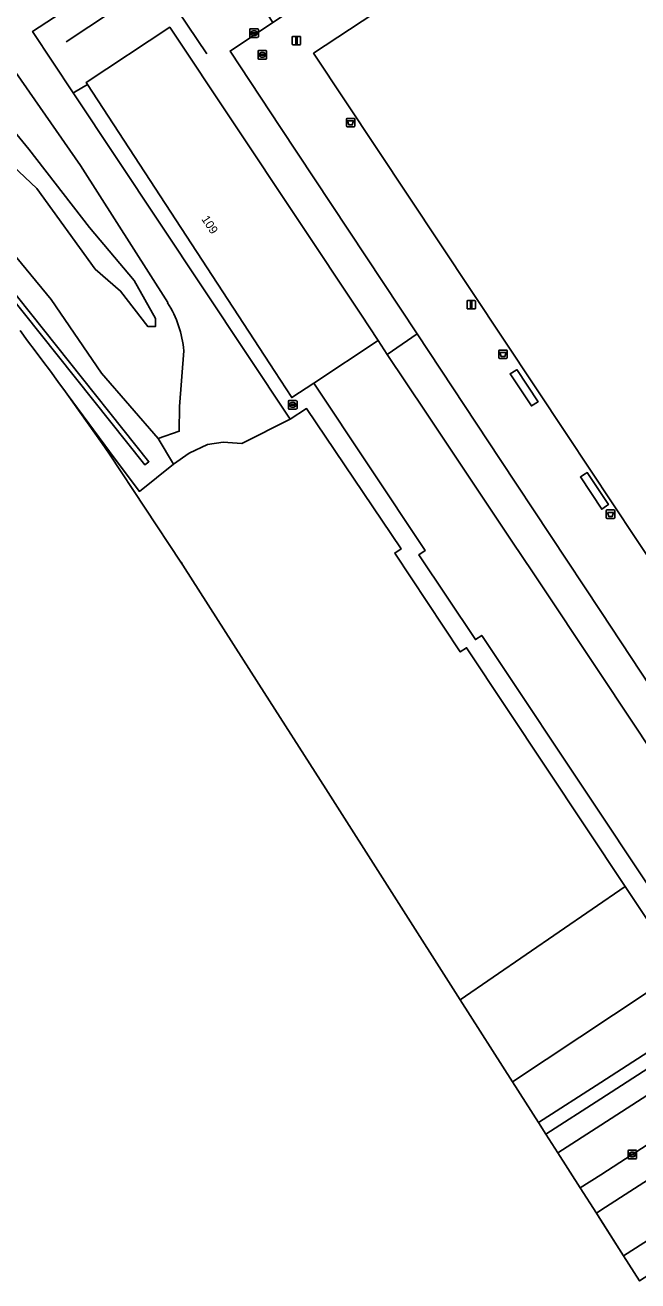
# Model space of a CAD drawing. Extents: x 155640 to 156811, y 382821 to 384049.
# Drawn here: x 156432.6 to 156504.4, y 382835.2 to 382982.3 of the extents above; entities that cross this region are included whole.
import ezdxf

# ---------------------------------------------------------------- set-up
doc = ezdxf.new("R2010")
doc.units = 0
for name, color, linetype in [('IMGEO_Afvalbak', 7, 'Continuous'), ('IMGEO_Berm_groen', 7, 'Continuous'), ('IMGEO_Erf', 7, 'Continuous'), ('IMGEO_Fietspad_gesloten', 7, 'Continuous'), ('IMGEO_Groenvoorziening', 7, 'Continuous'), ('IMGEO_Hek', 7, 'Continuous'), ('IMGEO_Kolk', 7, 'Continuous'), ('IMGEO_Lichtmast', 7, 'Continuous'), ('IMGEO_Pand', 7, 'Continuous'), ('IMGEO_Pand_nummerreeks', 7, 'Continuous'), ('IMGEO_Rijbaan_regionaal_gesloten', 7, 'Continuous'), ('IMGEO_Rioolput', 7, 'Continuous'), ('IMGEO_Terreindeel_gesloten', 7, 'Continuous'), ('IMGEO_Voetpad_gesloten', 7, 'Continuous'), ('IMGEO_Voetpad_open', 7, 'Continuous')]:
    doc.layers.add(name, color=color, linetype=linetype)

msp = doc.modelspace()

# ---------------------------------------------------------------- linework, layer by layer
at = {"layer": 'IMGEO_Afvalbak'}
for p, q in [((156470.21, 382970.51), (156470.21, 382971.31)), ((156470.21, 382971.31), (156470.21, 382970.51)), ((156470.31, 382971.41), (156471.09, 382971.41)), ((156471.09, 382971.41), (156470.31, 382971.41)), ((156471.09, 382970.41), (156470.31, 382970.41)), ((156470.31, 382970.41), (156471.09, 382970.41)), ((156471.19, 382971.31), (156471.19, 382970.51)), ((156471.19, 382970.51), (156471.19, 382971.31)), ((156488.06, 382943.37), (156488.06, 382944.17)), ((156488.06, 382944.17), (156488.06, 382943.37)), ((156488.16, 382944.27), (156488.95, 382944.27)), ((156488.95, 382944.27), (156488.16, 382944.27)), ((156489.05, 382944.17), (156489.05, 382943.37)), ((156489.05, 382943.37), (156489.05, 382944.17)), ((156488.95, 382943.27), (156488.16, 382943.27)), ((156488.16, 382943.27), (156488.95, 382943.27)), ((156500.65, 382924.64), (156500.65, 382925.44)), ((156500.65, 382925.44), (156500.65, 382924.64)), ((156500.75, 382925.54), (156501.54, 382925.54)), ((156501.54, 382925.54), (156500.75, 382925.54)), ((156501.64, 382925.44), (156501.64, 382924.64)), ((156501.64, 382924.64), (156501.64, 382925.44)), ((156501.54, 382924.54), (156500.75, 382924.54)), ((156500.75, 382924.54), (156501.54, 382924.54))]:
    msp.add_line(p, q, dxfattribs=at)
for points in [[(156470.35, 382971.13), (156471.05, 382971.13), (156470.9, 382970.65), (156470.5, 382970.65), (156470.35, 382971.13)], [(156488.2, 382943.99), (156488.91, 382943.99), (156488.76, 382943.51), (156488.35, 382943.51), (156488.2, 382943.99)], [(156500.79, 382925.25), (156501.5, 382925.25), (156501.35, 382924.78), (156500.94, 382924.78), (156500.79, 382925.25)]]:
    msp.add_lwpolyline(points, dxfattribs=at)
for centre, start, end in [((156470.31, 382971.31), 90, 180), ((156470.31, 382971.31), 90, 180), ((156470.31, 382970.51), 180, 270), ((156470.31, 382970.51), 180, 270), ((156471.09, 382971.31), 0, 90), ((156471.09, 382971.31), 360, 90), ((156471.09, 382970.51), 270, 0), ((156471.09, 382970.51), 270, 0), ((156488.16, 382944.17), 90, 180), ((156488.16, 382944.17), 90, 180), ((156488.95, 382944.17), 0, 90), ((156488.95, 382944.17), 360, 90), ((156488.16, 382943.37), 180, 270), ((156488.16, 382943.37), 180, 270), ((156488.95, 382943.37), 270, 0), ((156488.95, 382943.37), 270, 0), ((156500.75, 382925.44), 90, 180), ((156500.75, 382925.44), 90, 180), ((156501.54, 382925.44), 0, 90), ((156501.54, 382925.44), 360, 90), ((156500.75, 382924.64), 180, 270), ((156500.75, 382924.64), 180, 270), ((156501.54, 382924.64), 270, 0), ((156501.54, 382924.64), 270, 0)]:
    msp.add_arc(centre, 0.1, start, end, dxfattribs=at)
at = {"layer": 'IMGEO_Berm_groen'}
for points in [[(156551.36, 382886.6), (156549.21, 382885.22), (156500, 382853.47), (156494.97, 382850.22), (156497.6, 382846.1), (156500, 382847.64), (156503.7, 382850.02), (156518.86, 382859.79), (156534.39, 382869.79), (156551.62, 382880.87)], [(156556.43, 382879.8), (156500, 382843.48)], [(156500, 382843.48), (156499.49, 382843.15), (156502.68, 382838.15), (156506.01, 382840.3), (156509.37, 382842.45), (156512.6, 382844.84), (156532.14, 382860.54)]]:
    msp.add_lwpolyline(points, dxfattribs=at)
at = {"layer": 'IMGEO_Erf'}
msp.add_lwpolyline([(156450.82, 382919.42), (156450.83, 382919.42), (156451.06, 382919.06), (156451.06, 382919.06), (156459.96, 382905.11), (156467.78, 382892.85), (156467.78, 382892.85), (156483.53, 382868.15), (156502.87, 382881.43), (156484.28, 382909.39), (156483.55, 382908.9), (156475.87, 382920.48), (156476.61, 382920.96), (156465.54, 382937.4), (156463.61, 382936.15), (156457.95, 382933.32), (156455.75, 382933.47), (156453.93, 382933.22), (156451.77, 382932.2), (156449.96, 382930.89), (156445.96, 382927.71), (156443.13, 382931.5), (156437.49, 382939.08), (156438.16, 382938.16), (156439.02, 382936.95), (156439.89, 382935.73), (156440.74, 382934.52), (156441.6, 382933.3), (156442.45, 382932.07)], close=True, dxfattribs=at)
at = {"layer": 'IMGEO_Fietspad_gesloten'}
msp.add_lwpolyline([(156548.16, 382887.64), (156500, 382856.53), (156493.59, 382852.39), (156494.97, 382850.22), (156500, 382853.47), (156549.21, 382885.22), (156551.36, 382886.6)], dxfattribs=at)
at = {"layer": 'IMGEO_Groenvoorziening'}
for points in [[(156251.71, 383103.22), (156317.77, 383054.79), (156319.51, 383051.96), (156359.06, 383022.72), (156397.9, 382989.3), (156414.08, 382971.59), (156446.59, 382930.82), (156447.07, 382931.18), (156414.55, 382971.96), (156398.38, 382989.67), (156359.53, 383023.09), (156319.98, 383052.32), (156318.24, 383055.16), (156252.18, 383103.58), (156251.81, 383103.29)], [(156359.53, 383023.09), (156398.38, 382989.67), (156414.55, 382971.96), (156447.07, 382931.18), (156446.59, 382930.82), (156414.08, 382971.59), (156397.9, 382989.3), (156359.06, 383022.72), (156319.51, 383051.96), (156317.77, 383054.79), (156251.71, 383103.22), (156251.81, 383103.29), (156252.18, 383103.58), (156318.24, 383055.16), (156319.98, 383052.32)], [(156483.53, 382868.15), (156489.68, 382858.52), (156509.39, 382871.62), (156502.87, 382881.43)], [(156499.49, 382843.15), (156500, 382842.34), (156502.68, 382838.15)]]:
    msp.add_lwpolyline(points, close=True, dxfattribs=at)
for points in [[(156255.05, 383103.49), (156264.43, 383096.48), (156294.23, 383074.54), (156313.79, 383060.73), (156336.14, 383043.58), (156363.98, 383022.66), (156379.55, 383010.3), (156403.91, 382988.08), (156421.5, 382967.29), (156435.6, 382950.17), (156441.51, 382941.55), (156448.16, 382933.9), (156450.62, 382934.76), (156450.67, 382937.67), (156451.15, 382944.19)], [(156451.15, 382944.19), (156450.67, 382937.67), (156450.62, 382934.76), (156448.16, 382933.9), (156449.96, 382930.89), (156451.77, 382932.2), (156453.93, 382933.22), (156455.75, 382933.47), (156457.95, 382933.32), (156463.61, 382936.15), (156438.21, 382974.39), (156433.44, 382981.59), (156440.92, 382986.52), (156439.33, 382988.35), (156371.47, 383038.23)], [(156449.27, 382949.82), (156439.05, 382965.88), (156430.86, 382977.69), (156429.53, 382979.73), (156426.61, 382985.01)], [(156426.61, 382985.01), (156429.53, 382979.73), (156430.86, 382977.69), (156439.05, 382965.88), (156449.27, 382949.82)], [(156421.12, 382975.25), (156433.92, 382963.21), (156440.78, 382953.74), (156443.76, 382951.17), (156446.93, 382947.03), (156447.86, 382947.03), (156447.86, 382947.96), (156445.36, 382952.4), (156440.09, 382958.61), (156433.01, 382967.82), (156425.56, 382976.88)], [(156425.56, 382976.88), (156433.01, 382967.82), (156440.09, 382958.61), (156445.36, 382952.4), (156447.86, 382947.96), (156447.86, 382947.03), (156446.93, 382947.03), (156443.76, 382951.17), (156440.78, 382953.74), (156433.92, 382963.21), (156421.12, 382975.25)], [(156431.97, 382946.55), (156432.86, 382945.36), (156433.76, 382944.17), (156434.65, 382942.98), (156435.53, 382941.78), (156436.41, 382940.58), (156437.29, 382939.37), (156437.49, 382939.08), (156443.13, 382931.5), (156445.96, 382927.71), (156449.96, 382930.89), (156448.16, 382933.9), (156441.51, 382941.55), (156435.6, 382950.17), (156421.5, 382967.29)], [(156591.61, 382925.65), (156590.83, 382925.47), (156590.77, 382925.43), (156590.12, 382924.99), (156522.16, 382880.06), (156511.09, 382872.74), (156509.39, 382871.62), (156489.68, 382858.52), (156492.71, 382853.76), (156500, 382858.46), (156547.39, 382889.03)]]:
    msp.add_lwpolyline(points, dxfattribs=at)
msp.add_arc((156438.83, 382943.19), 12.36, 4.6367, 32.4104, dxfattribs=at)
msp.add_arc((156438.83, 382943.19), 12.36, 4.6367, 32.4104, dxfattribs=at)
at = {"layer": 'IMGEO_Hek'}
for points in [[(156439.33, 382988.35), (156440.92, 382986.52), (156433.44, 382981.59), (156438.21, 382974.39)], [(156437.38, 382980.39), (156448.13, 382987.51), (156453.85, 382978.96)], [(156438.36, 382974.48), (156439.88, 382975.38)], [(156438.21, 382974.39), (156438.36, 382974.48)], [(156438.21, 382974.39), (156463.61, 382936.15), (156465.54, 382937.4), (156476.61, 382920.96)], [(156443.13, 382931.5), (156437.49, 382939.08)], [(156476.61, 382920.96), (156475.87, 382920.48), (156483.55, 382908.9), (156484.28, 382909.39), (156502.87, 382881.43), (156509.39, 382871.62)]]:
    msp.add_lwpolyline(points, dxfattribs=at)
at = {"layer": 'IMGEO_Kolk'}
for p, q in [((156459.86, 382978.43), (156459.86, 382979.28)), ((156459.94, 382979.36), (156460.79, 382979.36)), ((156460.86, 382979.28), (156460.86, 382978.43)), ((156460.79, 382978.35), (156459.94, 382978.35)), ((156460.12, 382978.85), (156460.12, 382978.86)), ((156460.16, 382978.9), (156460.56, 382978.9)), ((156460.56, 382978.81), (156460.16, 382978.81)), ((156460.35, 382979.13), (156460.37, 382979.13)), ((156460.37, 382978.58), (156460.35, 382978.58)), ((156460.6, 382978.86), (156460.6, 382978.85)), ((156503.2, 382849.59), (156503.2, 382850.44)), ((156503.28, 382850.52), (156504.13, 382850.52)), ((156503.46, 382850.01), (156503.46, 382850.02)), ((156503.5, 382850.06), (156503.9, 382850.06)), ((156503.9, 382849.97), (156503.5, 382849.97)), ((156503.69, 382850.3), (156503.72, 382850.3)), ((156503.71, 382849.74), (156503.69, 382849.74)), ((156503.95, 382850.02), (156503.95, 382850.01)), ((156504.2, 382850.44), (156504.2, 382849.59)), ((156504.13, 382849.52), (156503.28, 382849.52))]:
    msp.add_line(p, q, dxfattribs=at)
for points in [[(156459.86, 382978.43), (156459.86, 382979.28)], [(156459.94, 382979.36), (156460.79, 382979.36)], [(156460.86, 382979.28), (156460.86, 382978.43)], [(156460.79, 382978.35), (156459.94, 382978.35)], [(156503.2, 382849.59), (156503.2, 382850.44)], [(156503.28, 382850.52), (156504.13, 382850.52)], [(156504.2, 382850.44), (156504.2, 382849.59)], [(156504.13, 382849.52), (156503.28, 382849.52)]]:
    msp.add_lwpolyline(points, dxfattribs=at)
for centre, radius, start, end in [((156459.94, 382979.28), 0.0765, 91.552, 178.448), ((156459.94, 382979.28), 0.0765, 91.552, 178.448), ((156460.79, 382979.28), 0.0765, 1.552, 88.448), ((156460.79, 382979.28), 0.0765, 1.552, 88.448), ((156459.94, 382978.43), 0.0765, 181.552, 268.448), ((156459.94, 382978.43), 0.0765, 181.552, 268.448), ((156460.16, 382978.86), 0.0403, 85.8775, 175.7526), ((156460.16, 382978.85), 0.0366, 178.938, 274.7102), ((156460.57, 382978.86), 0.0386, 1.7309, 96.639), ((156460.56, 382978.85), 0.043, 264.8664, 352.4533), ((156460.79, 382978.43), 0.0765, 271.552, 358.448), ((156460.79, 382978.43), 0.0765, 271.552, 358.448), ((156503.28, 382850.44), 0.0765, 91.552, 178.448), ((156503.28, 382850.44), 0.0765, 91.552, 178.448), ((156503.5, 382850.02), 0.0403, 85.8775, 175.7526), ((156503.5, 382850.01), 0.0366, 178.938, 274.7102), ((156503.91, 382850.02), 0.0386, 1.7309, 96.639), ((156503.9, 382850.02), 0.043, 264.8664, 352.4533), ((156504.13, 382850.44), 0.0765, 1.552, 88.448), ((156504.13, 382850.44), 0.0765, 1.552, 88.448), ((156503.28, 382849.59), 0.0765, 181.552, 268.448), ((156503.28, 382849.59), 0.0765, 181.552, 268.448), ((156504.13, 382849.59), 0.0765, 271.552, 358.448), ((156504.13, 382849.59), 0.0765, 271.552, 358.448)]:
    msp.add_arc(centre, radius, start, end, dxfattribs=at)
for centre, major_axis, ratio, start_param, end_param in [((156460.35, 382978.85), (-0.387, 0.002), 0.722429, 4.712389, 7.853982), ((156460.37, 382978.85), (-0.39, 0.002), 0.717154, 1.570796, 4.712389), ((156503.69, 382850.02), (-0.387, 0.002), 0.722429, 4.712389, 7.853982), ((156503.71, 382850.02), (-0.39, 0.002), 0.717154, 1.570796, 4.712389)]:
    msp.add_ellipse(centre, major_axis=major_axis, ratio=ratio, start_param=start_param, end_param=end_param, dxfattribs=at)
at = {"layer": 'IMGEO_Lichtmast'}
for p, q in [((156463.85, 382980.12), (156463.85, 382980.92)), ((156463.85, 382980.92), (156463.85, 382980.12)), ((156463.95, 382981.02), (156464.74, 382981.02)), ((156464.74, 382981.02), (156463.95, 382981.02)), ((156464.84, 382980.92), (156464.84, 382980.12)), ((156464.84, 382980.12), (156464.84, 382980.92)), ((156464.74, 382980.02), (156463.95, 382980.02)), ((156463.95, 382980.02), (156464.74, 382980.02)), ((156484.34, 382949.18), (156484.34, 382949.97)), ((156484.34, 382949.97), (156484.34, 382949.18)), ((156484.44, 382950.07), (156485.22, 382950.07)), ((156485.22, 382950.07), (156484.44, 382950.07)), ((156485.32, 382949.97), (156485.32, 382949.18)), ((156485.32, 382949.18), (156485.32, 382949.97)), ((156485.22, 382949.08), (156484.44, 382949.08)), ((156484.44, 382949.08), (156485.22, 382949.08))]:
    msp.add_line(p, q, dxfattribs=at)
for points in [[(156464.27, 382980.89), (156464.42, 382980.89), (156464.42, 382980.14), (156464.27, 382980.14), (156464.27, 382980.89)], [(156484.75, 382949.95), (156484.9, 382949.95), (156484.9, 382949.2), (156484.75, 382949.2), (156484.75, 382949.95)]]:
    msp.add_lwpolyline(points, dxfattribs=at)
for centre, start, end in [((156463.95, 382980.92), 90, 180), ((156463.95, 382980.92), 90, 180), ((156464.74, 382980.92), 0, 90), ((156464.74, 382980.92), 360, 90), ((156463.95, 382980.12), 180, 270), ((156463.95, 382980.12), 180, 270), ((156464.74, 382980.12), 270, 0), ((156464.74, 382980.12), 270, 0), ((156484.44, 382949.97), 90, 180), ((156484.44, 382949.97), 90, 180), ((156485.22, 382949.97), 0, 90), ((156485.22, 382949.97), 360, 90), ((156484.44, 382949.18), 180, 270), ((156484.44, 382949.18), 180, 270), ((156485.22, 382949.18), 270, 0), ((156485.22, 382949.18), 270, 0)]:
    msp.add_arc(centre, 0.1, start, end, dxfattribs=at)
at = {"layer": 'IMGEO_Pand'}
for points in [[(156473.92, 382945.39), (156471.89, 382948.48), (156449.52, 382982.08), (156439.73, 382975.62), (156439.88, 382975.38), (156461.81, 382941.76), (156463.81, 382938.7), (156466.41, 382940.4)], [(156473.92, 382945.39), (156466.41, 382940.4), (156479.45, 382920.79), (156478.71, 382920.29), (156485.32, 382910.34), (156486.07, 382910.84), (156500, 382889.89), (156508.36, 382877.32), (156515.9, 382882.33), (156500, 382906.24), (156492.07, 382918.15), (156489.6, 382921.86), (156479.53, 382936.97), (156475, 382943.76)], [(156450.82, 382919.42), (156451.06, 382919.06), (156450.83, 382919.42)], [(156467.78, 382892.85), (156467.78, 382892.85), (156459.96, 382905.11)]]:
    msp.add_lwpolyline(points, close=True, dxfattribs=at)
at = {"layer": 'IMGEO_Rijbaan_regionaal_gesloten'}
for points in [[(156551.62, 382880.87), (156534.39, 382869.79), (156518.86, 382859.79), (156503.7, 382850.02), (156500, 382847.64), (156497.6, 382846.1), (156499.49, 382843.15), (156500, 382843.48), (156556.43, 382879.8)], [(156532.14, 382860.54), (156512.6, 382844.84), (156509.37, 382842.45), (156506.01, 382840.3), (156502.68, 382838.15), (156504.55, 382835.21), (156507.61, 382837.18), (156509.79, 382838.56), (156524.51, 382848.04), (156541.59, 382859.04), (156566.65, 382875.17), (156572.87, 382879.17)]]:
    msp.add_lwpolyline(points, dxfattribs=at)
at = {"layer": 'IMGEO_Rioolput'}
for p, q in [((156458.89, 382980.98), (156458.89, 382981.83)), ((156458.96, 382981.9), (156459.81, 382981.9)), ((156459.81, 382980.9), (156458.96, 382980.9)), ((156459.14, 382981.4), (156459.14, 382981.41)), ((156459.58, 382981.36), (156459.18, 382981.36)), ((156459.19, 382981.45), (156459.58, 382981.45)), ((156459.37, 382981.68), (156459.4, 382981.68)), ((156459.4, 382981.12), (156459.37, 382981.12)), ((156459.63, 382981.41), (156459.63, 382981.4)), ((156459.89, 382981.83), (156459.89, 382980.98)), ((156463.42, 382937.41), (156463.42, 382938.27)), ((156463.49, 382938.34), (156464.34, 382938.34)), ((156463.9, 382938.12), (156463.93, 382938.12)), ((156464.42, 382938.27), (156464.42, 382937.41)), ((156464.34, 382937.34), (156463.49, 382937.34)), ((156463.67, 382937.83), (156463.67, 382937.85)), ((156464.11, 382937.8), (156463.71, 382937.8)), ((156463.72, 382937.88), (156464.11, 382937.88)), ((156463.93, 382937.56), (156463.9, 382937.56)), ((156464.16, 382937.85), (156464.16, 382937.83))]:
    msp.add_line(p, q, dxfattribs=at)
for points in [[(156458.89, 382980.98), (156458.89, 382981.83)], [(156458.96, 382981.9), (156459.81, 382981.9)], [(156459.81, 382980.9), (156458.96, 382980.9)], [(156459.89, 382981.83), (156459.89, 382980.98)], [(156463.42, 382937.41), (156463.42, 382938.27)], [(156463.49, 382938.34), (156464.34, 382938.34)], [(156464.42, 382938.27), (156464.42, 382937.41)], [(156464.34, 382937.34), (156463.49, 382937.34)]]:
    msp.add_lwpolyline(points, dxfattribs=at)
for centre, radius, start, end in [((156458.96, 382981.83), 0.0765, 91.552, 178.448), ((156458.96, 382981.83), 0.0765, 91.552, 178.448), ((156458.96, 382980.98), 0.0765, 181.552, 268.448), ((156458.96, 382980.98), 0.0765, 181.552, 268.448), ((156459.18, 382981.41), 0.0403, 85.8775, 175.7526), ((156459.18, 382981.4), 0.0366, 178.938, 274.7102), ((156459.59, 382981.41), 0.0386, 1.7309, 96.639), ((156459.59, 382981.4), 0.043, 264.8664, 352.4533), ((156459.81, 382981.83), 0.0765, 1.552, 88.448), ((156459.81, 382981.83), 0.0765, 1.552, 88.448), ((156459.81, 382980.98), 0.0765, 271.552, 358.448), ((156459.81, 382980.98), 0.0765, 271.552, 358.448), ((156463.49, 382938.27), 0.0765, 91.552, 178.448), ((156463.49, 382938.27), 0.0765, 91.552, 178.448), ((156464.34, 382938.27), 0.0765, 1.552, 88.448), ((156464.34, 382938.27), 0.0765, 1.552, 88.448), ((156463.49, 382937.42), 0.0765, 181.552, 268.448), ((156463.49, 382937.42), 0.0765, 181.552, 268.448), ((156463.71, 382937.84), 0.0403, 85.8775, 175.7526), ((156463.71, 382937.83), 0.0366, 178.938, 274.7102), ((156464.12, 382937.85), 0.0386, 1.7309, 96.639), ((156464.12, 382937.84), 0.043, 264.8664, 352.4533), ((156464.34, 382937.42), 0.0765, 271.552, 358.448), ((156464.34, 382937.42), 0.0765, 271.552, 358.448)]:
    msp.add_arc(centre, radius, start, end, dxfattribs=at)
for centre, major_axis, ratio, start_param, end_param in [((156459.37, 382981.4), (-0.387, 0.002), 0.722429, 4.712389, 7.853982), ((156459.4, 382981.4), (-0.39, 0.002), 0.717154, 1.570796, 4.712389), ((156463.9, 382937.84), (-0.387, 0.002), 0.722429, 4.712389, 7.853982), ((156463.93, 382937.84), (-0.39, 0.002), 0.717154, 1.570796, 4.712389)]:
    msp.add_ellipse(centre, major_axis=major_axis, ratio=ratio, start_param=start_param, end_param=end_param, dxfattribs=at)
at = {"layer": 'IMGEO_Terreindeel_gesloten'}
msp.add_lwpolyline([(156525.79, 383018.26), (156496.11, 382998.65), (156466.37, 382979.03), (156496.03, 382934.37), (156525.68, 382889.7), (156554.95, 382909.05), (156585.09, 382928.93), (156555.47, 382973.61)], close=True, dxfattribs=at)
at = {"layer": 'IMGEO_Voetpad_gesloten'}
msp.add_lwpolyline([(156466.41, 382940.4), (156463.81, 382938.7), (156461.81, 382941.76), (156439.88, 382975.38), (156438.36, 382974.48), (156438.21, 382974.39), (156463.61, 382936.15), (156465.54, 382937.4), (156476.61, 382920.96), (156475.87, 382920.48), (156483.55, 382908.9), (156484.28, 382909.39), (156502.87, 382881.43), (156509.39, 382871.62), (156511.09, 382872.74), (156508.18, 382877.21), (156508.36, 382877.32), (156500, 382889.89), (156486.07, 382910.84), (156485.32, 382910.34), (156478.71, 382920.29), (156479.45, 382920.79)], close=True, dxfattribs=at)
at = {"layer": 'IMGEO_Voetpad_open'}
for points in [[(156371.47, 383038.23), (156439.33, 382988.35), (156440.92, 382986.52), (156433.44, 382981.59), (156438.21, 382974.39), (156438.36, 382974.48), (156439.88, 382975.38), (156439.73, 382975.62), (156449.52, 382982.08), (156471.89, 382948.48), (156473.92, 382945.39), (156475, 382943.76), (156478.48, 382946.18), (156462.49, 382970.34), (156456.57, 382979.3), (156461.58, 382982.63), (156458.49, 382987.4)], [(156547.39, 382889.03), (156500, 382858.46), (156492.71, 382853.76), (156493.59, 382852.39)], [(156493.59, 382852.39), (156500, 382856.53), (156548.16, 382887.64)]]:
    msp.add_lwpolyline(points, dxfattribs=at)
for points in [[(156590.12, 382924.99), (156590.77, 382925.43), (156586.12, 382932.44), (156566.87, 382961.46), (156551.93, 382983.96), (156547.45, 382990.71), (156541.27, 383000), (156526.17, 383022.74), (156524.88, 383024.63), (156524.29, 383024.2), (156508.86, 383013.97), (156507.8, 383013.27), (156500, 383008.1), (156487.79, 383000), (156461.58, 382982.63), (156456.57, 382979.3), (156462.49, 382970.34), (156478.48, 382946.18), (156488.24, 382931.43), (156500, 382913.62), (156522.16, 382880.06)], [(156525.68, 382889.7), (156496.03, 382934.37), (156466.37, 382979.03), (156496.11, 382998.65), (156525.79, 383018.26), (156555.47, 382973.61), (156585.09, 382928.93), (156554.95, 382909.05)], [(156488.24, 382931.43), (156478.48, 382946.18), (156475, 382943.76), (156479.53, 382936.97), (156489.6, 382921.86), (156492.07, 382918.15), (156500, 382906.24), (156515.9, 382882.33), (156508.36, 382877.32), (156508.18, 382877.21), (156511.09, 382872.74), (156522.16, 382880.06), (156500, 382913.62)], [(156489.39, 382941.48), (156491.89, 382937.72), (156492.59, 382938.16), (156492.67, 382938.21), (156490.17, 382941.97), (156490.1, 382941.92)], [(156492.59, 382938.16), (156491.89, 382937.72), (156489.39, 382941.48), (156490.1, 382941.92), (156490.17, 382941.97), (156492.67, 382938.21)], [(156498.42, 382929.91), (156498.18, 382929.77), (156497.62, 382929.41), (156500.13, 382925.62), (156500.68, 382926.01), (156500.91, 382926.17)], [(156500.68, 382926.01), (156500.13, 382925.62), (156497.62, 382929.41), (156498.18, 382929.77), (156498.42, 382929.91), (156500.91, 382926.17)]]:
    msp.add_lwpolyline(points, close=True, dxfattribs=at)

# ---------------------------------------------------------------- texts
at = {"layer": 'IMGEO_Pand_nummerreeks'}
msp.add_text('109', height=1, rotation=303.1205, dxfattribs=at).set_placement((156453.18, 382959.62))

doc.saveas('drawing.dxf')
